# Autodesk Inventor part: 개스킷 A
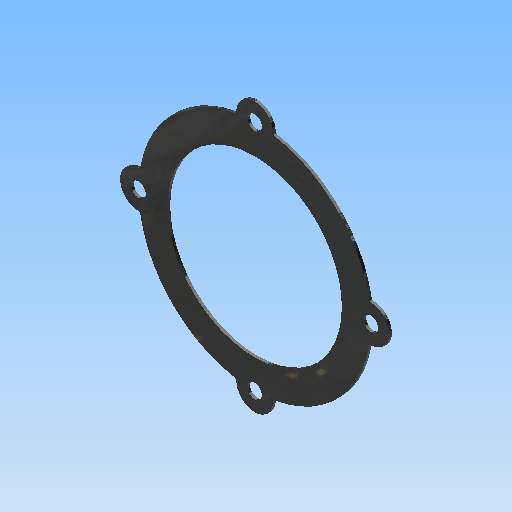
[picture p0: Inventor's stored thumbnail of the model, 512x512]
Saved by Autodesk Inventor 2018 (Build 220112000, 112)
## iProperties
Created: 2020-03
Part Number: 개스킷 A
Material: 고무
Document SubType Name: Modeling
Designer: mduedu
Density: 0.93 g/cm^3
Mass: 2.68337 g
Surface Area: 63.575 cm^2
Volume: 2.88534 cm^3
Appearance: 고무 - 검은색 - 버전 1.1
Author: mduedu
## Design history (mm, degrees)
sketch "스케치1" dims "d1" = 88
  geometry: C1 r 33 at (0, 0); C2 r 7 at (0, 44); C3 r 7 at (-38.105, -22); C4 r 7 at (38.105, -22); 2 further points
  constraints: 4 centre point, 2 coincident, 2 vertical alignment, 9 other
  dimensions: "d0" = 66 diameter of C1; "d2" = 14 diameter of C2; "d5" = 360 deg dimension on point (0, 0) C2.centre (derived)
extrude "돌출1" new body sketch "스케치1" distance "d7" = 1; taper "d8" = 0 deg
extrude "돌출2" join sketch "스케치1" stored distance "d17" = 10; taper "d18" = 0 deg
fillet "모깎기1" dims "d9" = 1
sketch "스케치2"
  geometry: C1 r 33 at (0, 0) reference; A1 r 44 centre (0, 0) between (-7.817, 43.3) and (7.817, 43.3) reference; A2 r 7 centre (0, 44) between (6.996, 44.249) and (-6.996, 44.249) reference; A3 r 1 centre (7.995, 44.284) between (6.996, 44.249) and (7.817, 43.3) reference; A4 r 1 centre (-7.995, 44.284) between (-7.817, 43.3) and (-6.996, 44.249) reference; 4 further points
hole "구멍1" sketch "스케치2" diameter "d10" = 5.5; stored, may be unused: countersink angle "d14" = 90 deg, drill point angle "d16" = 118 deg; dims "d11" = 6, "d12" = 10, "d13" = 5.7, "d15" = 8
node "솔리드1"
pattern_circular "원형 패턴1" dims angle "d20" = 360 deg
node "투영된 루프1"
